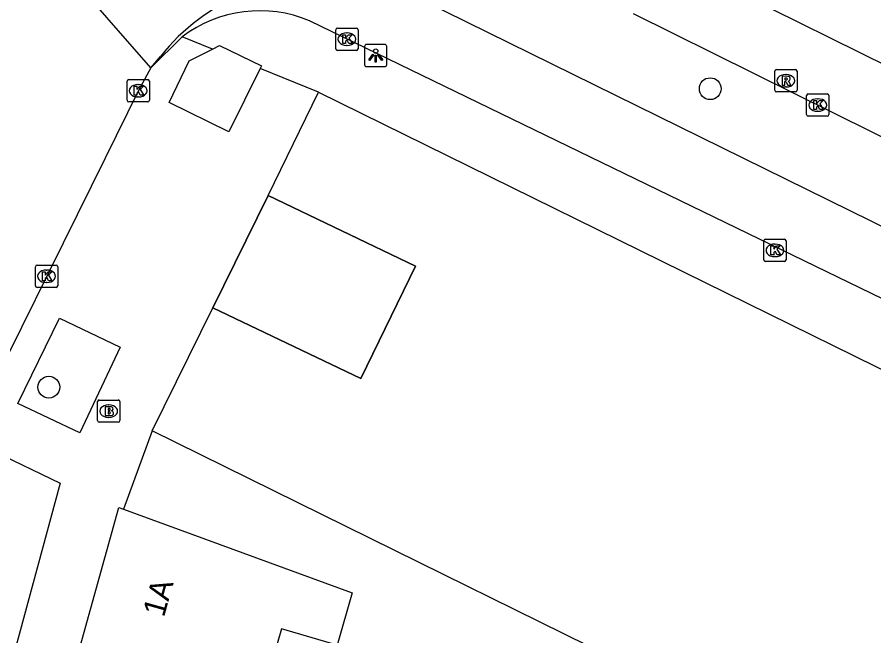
# Model space of a CAD drawing. Extents: x 159222 to 160346, y 381249 to 382166.
# Drawn here: x 160240.6 to 160279.06, y 382047.7 to 382075.48 of the extents above; entities that cross this region are included whole.
import ezdxf

# ---------------------------------------------------------------- set-up
doc = ezdxf.new("R2010")
doc.units = 0
for name, color, linetype in [('IMGEO_Boom', 7, 'Continuous'), ('IMGEO_Brandkraan', 7, 'Continuous'), ('IMGEO_Fietspad_open', 7, 'Continuous'), ('IMGEO_Kolk', 7, 'Continuous'), ('IMGEO_Lichtpunt', 7, 'Continuous'), ('IMGEO_Pand', 7, 'Continuous'), ('IMGEO_Pand_nummerreeks', 7, 'Continuous'), ('IMGEO_Pand_overbouw', 7, 'Continuous'), ('IMGEO_Rijbaan_lokaal_open', 7, 'Continuous'), ('IMGEO_Rijbaan_regionaal_gesloten', 7, 'Continuous'), ('IMGEO_Rioolput', 7, 'Continuous'), ('IMGEO_Voetpad_open', 7, 'Continuous')]:
    doc.layers.add(name, color=color, linetype=linetype)

msp = doc.modelspace()

# ---------------------------------------------------------------- linework, layer by layer
at = {"layer": 'IMGEO_Boom'}
for centre in [(160271.71, 382072.269), (160242.023, 382058.864)]:
    msp.add_circle(centre, 0.489, dxfattribs=at)
at = {"layer": 'IMGEO_Brandkraan'}
for p, q in [((160244.209, 382057.362), (160244.209, 382058.214)), ((160244.284, 382058.288), (160245.136, 382058.288)), ((160245.21, 382058.214), (160245.21, 382057.362)), ((160244.697, 382058.068), (160244.722, 382058.068)), ((160244.72, 382057.508), (160244.695, 382057.508)), ((160245.136, 382057.288), (160244.284, 382057.288))]:
    msp.add_line(p, q, dxfattribs=at)
for points in [[(160244.209, 382057.362), (160244.209, 382058.214)], [(160244.284, 382058.288), (160245.136, 382058.288)], [(160245.21, 382058.214), (160245.21, 382057.362)], [(160244.557, 382057.988), (160244.557, 382057.588), (160244.77, 382057.588)], [(160244.788, 382057.988), (160244.557, 382057.988)], [(160244.736, 382057.907), (160244.682, 382057.907), (160244.682, 382057.831)], [(160244.682, 382057.831), (160244.735, 382057.831)], [(160244.744, 382057.755), (160244.682, 382057.755), (160244.682, 382057.674)], [(160244.682, 382057.674), (160244.744, 382057.674)], [(160245.136, 382057.288), (160244.284, 382057.288)]]:
    msp.add_lwpolyline(points, dxfattribs=at)
for centre, radius, start, end in [((160244.286, 382058.212), 0.0765, 91.552, 178.448), ((160244.286, 382058.212), 0.0765, 91.552, 178.448), ((160245.134, 382058.212), 0.0765, 1.552, 88.448), ((160245.134, 382058.212), 0.0765, 1.552, 88.448), ((160244.737, 382057.869), 0.0379, 267.8285, 90.9355), ((160244.792, 382057.843), 0.145, 59.4692, 91.5367), ((160244.817, 382057.89), 0.0922, 285.5137, 58.1501), ((160244.745, 382057.714), 0.0404, 269.8759, 90.5077), ((160244.776, 382057.839), 0.251, 268.6676, 293.5347), ((160244.822, 382057.698), 0.105, 301.3115, 78.989), ((160244.286, 382057.364), 0.0765, 181.552, 268.448), ((160244.286, 382057.364), 0.0765, 181.552, 268.448), ((160245.134, 382057.364), 0.0765, 271.552, 358.448), ((160245.134, 382057.364), 0.0765, 271.552, 358.448)]:
    msp.add_arc(centre, radius, start, end, dxfattribs=at)
for centre, major_axis, ratio, start_param, end_param in [((160244.696, 382057.788), (-0.387, 0.002), 0.722429, 4.712389, 7.853982), ((160244.721, 382057.788), (-0.39, 0.002), 0.717154, 1.570796, 4.712389)]:
    msp.add_ellipse(centre, major_axis=major_axis, ratio=ratio, start_param=start_param, end_param=end_param, dxfattribs=at)
at = {"layer": 'IMGEO_Fietspad_open'}
for points in [[(160256.89, 382077.178), (160259.791, 382075.744), (160312.417, 382049.836), (160315.301, 382048.376)], [(160314.359, 382045.829), (160300.66, 382052.536), (160253.726, 382075.319)], [(160248.008, 382074.603), (160246.603, 382073.202)]]:
    msp.add_lwpolyline(points, dxfattribs=at)
msp.add_arc((160251.491, 382069.978), 5.79, 67.2914, 126.9833, dxfattribs=at)
at = {"layer": 'IMGEO_Kolk'}
for p, q in [((160254.901, 382074.065), (160254.901, 382074.917)), ((160254.976, 382074.991), (160255.828, 382074.991)), ((160255.389, 382074.771), (160255.414, 382074.771)), ((160255.902, 382074.917), (160255.902, 382074.065)), ((160255.828, 382073.991), (160254.976, 382073.991)), ((160255.412, 382074.211), (160255.387, 382074.211)), ((160245.534, 382071.75), (160245.534, 382072.602)), ((160245.609, 382072.676), (160246.461, 382072.676)), ((160246.022, 382072.456), (160246.047, 382072.456)), ((160246.535, 382072.602), (160246.535, 382071.75)), ((160246.461, 382071.676), (160245.609, 382071.676)), ((160246.045, 382071.896), (160246.02, 382071.896)), ((160276.036, 382071.109), (160276.036, 382071.961)), ((160276.111, 382072.035), (160276.963, 382072.035)), ((160276.524, 382071.815), (160276.549, 382071.815)), ((160277.037, 382071.961), (160277.037, 382071.109)), ((160276.963, 382071.035), (160276.111, 382071.035)), ((160276.547, 382071.255), (160276.522, 382071.255)), ((160274.115, 382064.583), (160274.115, 382065.435)), ((160274.19, 382065.509), (160275.042, 382065.509)), ((160274.603, 382065.289), (160274.628, 382065.289)), ((160275.116, 382065.435), (160275.116, 382064.583)), ((160275.042, 382064.509), (160274.19, 382064.509)), ((160274.626, 382064.729), (160274.601, 382064.729)), ((160241.419, 382063.417), (160241.419, 382064.269)), ((160241.494, 382064.343), (160242.346, 382064.343)), ((160241.907, 382064.123), (160241.932, 382064.123)), ((160242.42, 382064.269), (160242.42, 382063.417)), ((160242.346, 382063.343), (160241.494, 382063.343)), ((160241.93, 382063.563), (160241.905, 382063.563))]:
    msp.add_line(p, q, dxfattribs=at)
for points in [[(160254.901, 382074.065), (160254.901, 382074.917)], [(160254.976, 382074.991), (160255.828, 382074.991)], [(160255.902, 382074.917), (160255.902, 382074.065)], [(160255.222, 382074.691), (160255.345, 382074.691), (160255.345, 382074.54), (160255.475, 382074.691), (160255.639, 382074.691), (160255.493, 382074.54), (160255.646, 382074.291), (160255.494, 382074.291), (160255.409, 382074.455), (160255.345, 382074.388), (160255.345, 382074.291), (160255.222, 382074.291), (160255.222, 382074.691)], [(160255.828, 382073.991), (160254.976, 382073.991)], [(160245.534, 382071.75), (160245.534, 382072.602)], [(160245.609, 382072.676), (160246.461, 382072.676)], [(160246.535, 382072.602), (160246.535, 382071.75)], [(160245.855, 382072.376), (160245.978, 382072.376), (160245.978, 382072.225), (160246.108, 382072.376), (160246.272, 382072.376), (160246.126, 382072.225), (160246.279, 382071.976), (160246.127, 382071.976), (160246.042, 382072.14), (160245.978, 382072.073), (160245.978, 382071.976), (160245.855, 382071.976), (160245.855, 382072.376)], [(160246.461, 382071.676), (160245.609, 382071.676)], [(160276.036, 382071.109), (160276.036, 382071.961)], [(160276.111, 382072.035), (160276.963, 382072.035)], [(160276.357, 382071.735), (160276.48, 382071.735), (160276.48, 382071.584), (160276.61, 382071.735), (160276.774, 382071.735), (160276.628, 382071.584), (160276.781, 382071.335), (160276.629, 382071.335), (160276.544, 382071.499), (160276.48, 382071.432), (160276.48, 382071.335), (160276.357, 382071.335), (160276.357, 382071.735)], [(160277.037, 382071.961), (160277.037, 382071.109)], [(160276.963, 382071.035), (160276.111, 382071.035)], [(160274.115, 382064.583), (160274.115, 382065.435)], [(160274.19, 382065.509), (160275.042, 382065.509)], [(160274.436, 382065.209), (160274.559, 382065.209), (160274.559, 382065.058), (160274.689, 382065.209), (160274.853, 382065.209), (160274.707, 382065.058), (160274.86, 382064.809), (160274.708, 382064.809), (160274.623, 382064.973), (160274.559, 382064.906), (160274.559, 382064.809), (160274.436, 382064.809), (160274.436, 382065.209)], [(160275.116, 382065.435), (160275.116, 382064.583)], [(160275.042, 382064.509), (160274.19, 382064.509)], [(160241.419, 382063.417), (160241.419, 382064.269)], [(160241.494, 382064.343), (160242.346, 382064.343)], [(160241.74, 382064.043), (160241.863, 382064.043), (160241.863, 382063.892), (160241.993, 382064.043), (160242.157, 382064.043), (160242.011, 382063.892), (160242.164, 382063.643), (160242.012, 382063.643), (160241.927, 382063.807), (160241.863, 382063.74), (160241.863, 382063.643), (160241.74, 382063.643), (160241.74, 382064.043)], [(160242.42, 382064.269), (160242.42, 382063.417)], [(160242.346, 382063.343), (160241.494, 382063.343)]]:
    msp.add_lwpolyline(points, dxfattribs=at)
for centre, start, end in [((160254.978, 382074.915), 91.552, 178.448), ((160254.978, 382074.915), 91.552, 178.448), ((160255.826, 382074.915), 1.552, 88.448), ((160255.826, 382074.915), 1.552, 88.448), ((160254.978, 382074.067), 181.552, 268.448), ((160254.978, 382074.067), 181.552, 268.448), ((160255.826, 382074.067), 271.552, 358.448), ((160255.826, 382074.067), 271.552, 358.448), ((160245.611, 382072.6), 91.552, 178.448), ((160245.611, 382072.6), 91.552, 178.448), ((160246.459, 382072.6), 1.552, 88.448), ((160246.459, 382072.6), 1.552, 88.448), ((160245.611, 382071.752), 181.552, 268.448), ((160245.611, 382071.752), 181.552, 268.448), ((160246.459, 382071.752), 271.552, 358.448), ((160246.459, 382071.752), 271.552, 358.448), ((160276.113, 382071.959), 91.552, 178.448), ((160276.113, 382071.959), 91.552, 178.448), ((160276.961, 382071.959), 1.552, 88.448), ((160276.961, 382071.959), 1.552, 88.448), ((160276.113, 382071.111), 181.552, 268.448), ((160276.113, 382071.111), 181.552, 268.448), ((160276.961, 382071.111), 271.552, 358.448), ((160276.961, 382071.111), 271.552, 358.448), ((160274.192, 382065.433), 91.552, 178.448), ((160274.192, 382065.433), 91.552, 178.448), ((160275.04, 382065.433), 1.552, 88.448), ((160275.04, 382065.433), 1.552, 88.448), ((160274.192, 382064.585), 181.552, 268.448), ((160274.192, 382064.585), 181.552, 268.448), ((160275.04, 382064.585), 271.552, 358.448), ((160275.04, 382064.585), 271.552, 358.448), ((160241.496, 382064.267), 91.552, 178.448), ((160241.496, 382064.267), 91.552, 178.448), ((160242.344, 382064.267), 1.552, 88.448), ((160242.344, 382064.267), 1.552, 88.448), ((160241.496, 382063.419), 181.552, 268.448), ((160241.496, 382063.419), 181.552, 268.448), ((160242.344, 382063.419), 271.552, 358.448), ((160242.344, 382063.419), 271.552, 358.448)]:
    msp.add_arc(centre, 0.0765, start, end, dxfattribs=at)
for centre, major_axis, ratio, start_param, end_param in [((160255.388, 382074.491), (-0.387, 0.002), 0.722429, 4.712389, 7.853982), ((160255.413, 382074.491), (-0.39, 0.002), 0.717154, 1.570796, 4.712389), ((160246.021, 382072.176), (-0.387, 0.002), 0.722429, 4.712389, 7.853982), ((160246.046, 382072.176), (-0.39, 0.002), 0.717154, 1.570796, 4.712389), ((160276.523, 382071.535), (-0.387, 0.002), 0.722429, 4.712389, 7.853982), ((160276.548, 382071.535), (-0.39, 0.002), 0.717154, 1.570796, 4.712389), ((160274.602, 382065.009), (-0.387, 0.002), 0.722429, 4.712389, 7.853982), ((160274.627, 382065.009), (-0.39, 0.002), 0.717154, 1.570796, 4.712389), ((160241.906, 382063.843), (-0.387, 0.002), 0.722429, 4.712389, 7.853982), ((160241.931, 382063.843), (-0.39, 0.002), 0.717154, 1.570796, 4.712389)]:
    msp.add_ellipse(centre, major_axis=major_axis, ratio=ratio, start_param=start_param, end_param=end_param, dxfattribs=at)
at = {"layer": 'IMGEO_Lichtpunt'}
for p, q in [((160256.196, 382074.16), (160256.196, 382073.353)), ((160256.196, 382074.16), (160256.196, 382073.353)), ((160257.098, 382074.255), (160256.29, 382074.255)), ((160257.098, 382074.255), (160256.29, 382074.255)), ((160257.192, 382073.353), (160257.192, 382074.16)), ((160257.192, 382073.353), (160257.192, 382074.16)), ((160256.29, 382073.259), (160257.098, 382073.259)), ((160256.29, 382073.259), (160257.098, 382073.259))]:
    msp.add_line(p, q, dxfattribs=at)
for points in [[(160256.57, 382073.824), (160256.609, 382073.796), (160256.421, 382073.534), (160256.383, 382073.561), (160256.57, 382073.824)], [(160256.672, 382073.776), (160256.719, 382073.776), (160256.719, 382073.454), (160256.672, 382073.454), (160256.672, 382073.776)], [(160256.782, 382073.796), (160256.82, 382073.823), (160257.007, 382073.561), (160256.968, 382073.533), (160256.782, 382073.796)]]:
    msp.add_lwpolyline(points, dxfattribs=at)
msp.add_circle((160256.695, 382073.958), 0.0994, dxfattribs=at)
for centre, start, end in [((160256.29, 382074.16), 90, 180), ((160256.29, 382074.16), 90, 180), ((160257.098, 382074.16), 0, 90), ((160257.098, 382074.16), 0, 90), ((160256.29, 382073.353), 180, 270), ((160256.29, 382073.353), 180, 270), ((160257.098, 382073.353), 270, 0), ((160257.098, 382073.353), 270, 360)]:
    msp.add_arc(centre, 0.0946, start, end, dxfattribs=at)
at = {"layer": 'IMGEO_Pand'}
for points in [[(160251.863, 382067.479), (160254.125, 382072.109)], [(160254.125, 382072.109), (160299.362, 382049.833), (160312.584, 382043.36)], [(160251.863, 382067.479), (160258.484, 382064.296), (160256.031, 382059.248), (160249.382, 382062.43)], [(160246.663, 382056.903), (160249.382, 382062.43)], [(160317.304, 382036.313), (160317.288, 382036.188), (160314.558, 382030.651), (160311.74, 382024.945), (160305.022, 382028.184), (160305.63, 382029.445), (160280.178, 382042.019), (160279.523, 382040.691), (160279.111, 382040.894), (160276.024, 382042.417), (160246.663, 382056.903)], [(160243.274, 382046.684), (160245.168, 382053.456), (160245.377, 382053.38)], [(160245.377, 382053.38), (160255.639, 382049.633), (160254.96, 382047.285), (160252.469, 382048.006), (160251.405, 382044.329)]]:
    msp.add_lwpolyline(points, dxfattribs=at)
at = {"layer": 'IMGEO_Pand_overbouw'}
msp.add_lwpolyline([(160251.863, 382067.479), (160249.382, 382062.43), (160256.031, 382059.248), (160258.484, 382064.296)], close=True, dxfattribs=at)
at = {"layer": 'IMGEO_Rijbaan_lokaal_open'}
for points in [[(160246.603, 382073.202), (160240.567, 382080.128)], [(160246.603, 382073.202), (160247.032, 382073.719)], [(160246.603, 382073.202), (160246.042, 382072.193), (160244.545, 382069.152), (160231.992, 382043.761), (160231.719, 382042.87), (160231.528, 382041.958), (160231.418, 382041.032), (160231.391, 382040.1), (160231.434, 382039.313), (160231.475, 382038.801), (160231.563, 382038.294), (160231.695, 382037.798), (160231.87, 382037.315), (160232.089, 382036.849), (160232.237, 382036.584), (160232.307, 382036.466)]]:
    msp.add_lwpolyline(points, dxfattribs=at)
msp.add_arc((160254.272, 382067.988), 9.234, 111.995, 141.6381, dxfattribs=at)
at = {"layer": 'IMGEO_Rijbaan_regionaal_gesloten'}
for points in [[(160318.298, 382054.163), (160262.484, 382081.79), (160255.33, 382085.369), (160253.626, 382085.842)], [(160268.252, 382075.646), (160316.84, 382051.546)]]:
    msp.add_lwpolyline(points, dxfattribs=at)
at = {"layer": 'IMGEO_Rioolput'}
for p, q in [((160274.605, 382072.199), (160274.605, 382073.051)), ((160274.68, 382073.125), (160275.532, 382073.125)), ((160275.093, 382072.905), (160275.118, 382072.905)), ((160275.606, 382073.051), (160275.606, 382072.199)), ((160275.532, 382072.125), (160274.68, 382072.125)), ((160275.116, 382072.345), (160275.091, 382072.345))]:
    msp.add_line(p, q, dxfattribs=at)
for points in [[(160274.605, 382072.199), (160274.605, 382073.051)], [(160274.68, 382073.125), (160275.532, 382073.125)], [(160275.194, 382072.823), (160274.942, 382072.825), (160274.942, 382072.425)], [(160275.606, 382073.051), (160275.606, 382072.199)], [(160274.942, 382072.425), (160275.066, 382072.425), (160275.066, 382072.587), (160275.077, 382072.587)], [(160275.12, 382072.744), (160275.066, 382072.744), (160275.066, 382072.663)], [(160275.066, 382072.663), (160275.118, 382072.663)], [(160275.124, 382072.558), (160275.195, 382072.425), (160275.335, 382072.425), (160275.27, 382072.551)], [(160275.532, 382072.125), (160274.68, 382072.125)]]:
    msp.add_lwpolyline(points, dxfattribs=at)
for centre, radius, start, end in [((160274.682, 382073.049), 0.0765, 91.552, 178.448), ((160274.682, 382073.049), 0.0765, 91.552, 178.448), ((160275.193, 382072.713), 0.109, 350.3612, 89.416), ((160275.53, 382073.049), 0.0765, 1.552, 88.448), ((160275.53, 382073.049), 0.0765, 1.552, 88.448), ((160275.076, 382072.534), 0.0533, 26.0293, 88.6989), ((160275.102, 382072.852), 0.19, 274.7715, 282.9687), ((160275.126, 382072.648), 0.0964, 77.0061, 93.1865), ((160275.14, 382072.705), 0.0378, 276.6634, 79.6772), ((160275.191, 382072.713), 0.112, 277.5842, 350.9817), ((160275.175, 382072.498), 0.108, 29.5134, 73.7905), ((160274.682, 382072.201), 0.0765, 181.552, 268.448), ((160274.682, 382072.201), 0.0765, 181.552, 268.448), ((160275.53, 382072.201), 0.0765, 271.552, 358.448), ((160275.53, 382072.201), 0.0765, 271.552, 358.448)]:
    msp.add_arc(centre, radius, start, end, dxfattribs=at)
for centre, major_axis, ratio, start_param, end_param in [((160275.092, 382072.625), (-0.387, 0.002), 0.722429, 4.712389, 7.853982), ((160275.117, 382072.625), (-0.39, 0.002), 0.717154, 1.570796, 4.712389)]:
    msp.add_ellipse(centre, major_axis=major_axis, ratio=ratio, start_param=start_param, end_param=end_param, dxfattribs=at)
at = {"layer": 'IMGEO_Voetpad_open'}
for points in [[(160249.362, 382074.051), (160248.008, 382074.603)], [(160251.51, 382073.175), (160250.105, 382070.325), (160247.423, 382071.642), (160248.321, 382073.526), (160249.362, 382074.051)], [(160249.362, 382074.051), (160249.685, 382074.214), (160251.572, 382073.301), (160251.51, 382073.175)], [(160254.125, 382072.109), (160251.51, 382073.175)], [(160249.382, 382062.43), (160251.863, 382067.479)], [(160243.414, 382056.816), (160240.624, 382058.134), (160242.494, 382061.958), (160245.229, 382060.659), (160243.414, 382056.816)], [(160246.663, 382056.903), (160245.377, 382053.38)], [(160239.652, 382044.006), (160235.28, 382041.684), (160233.038, 382042.792), (160239.539, 382055.992), (160242.533, 382054.554), (160239.652, 382044.006)]]:
    msp.add_lwpolyline(points, dxfattribs=at)

# ---------------------------------------------------------------- texts
at = {"layer": 'IMGEO_Pand_nummerreeks'}
msp.add_text('1A', height=1, rotation=74.3757, dxfattribs=at).set_placement((160247.187, 382048.5))

doc.saveas('drawing.dxf')
